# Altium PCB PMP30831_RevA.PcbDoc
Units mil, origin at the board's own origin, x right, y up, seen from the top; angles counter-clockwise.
Board outline 4950 x 2150 mil, 2 copper layers (Top Layer, Bottom Layer), stack 62 mil thick; 78 components, 43 nets, 171 pads, 14 vias.
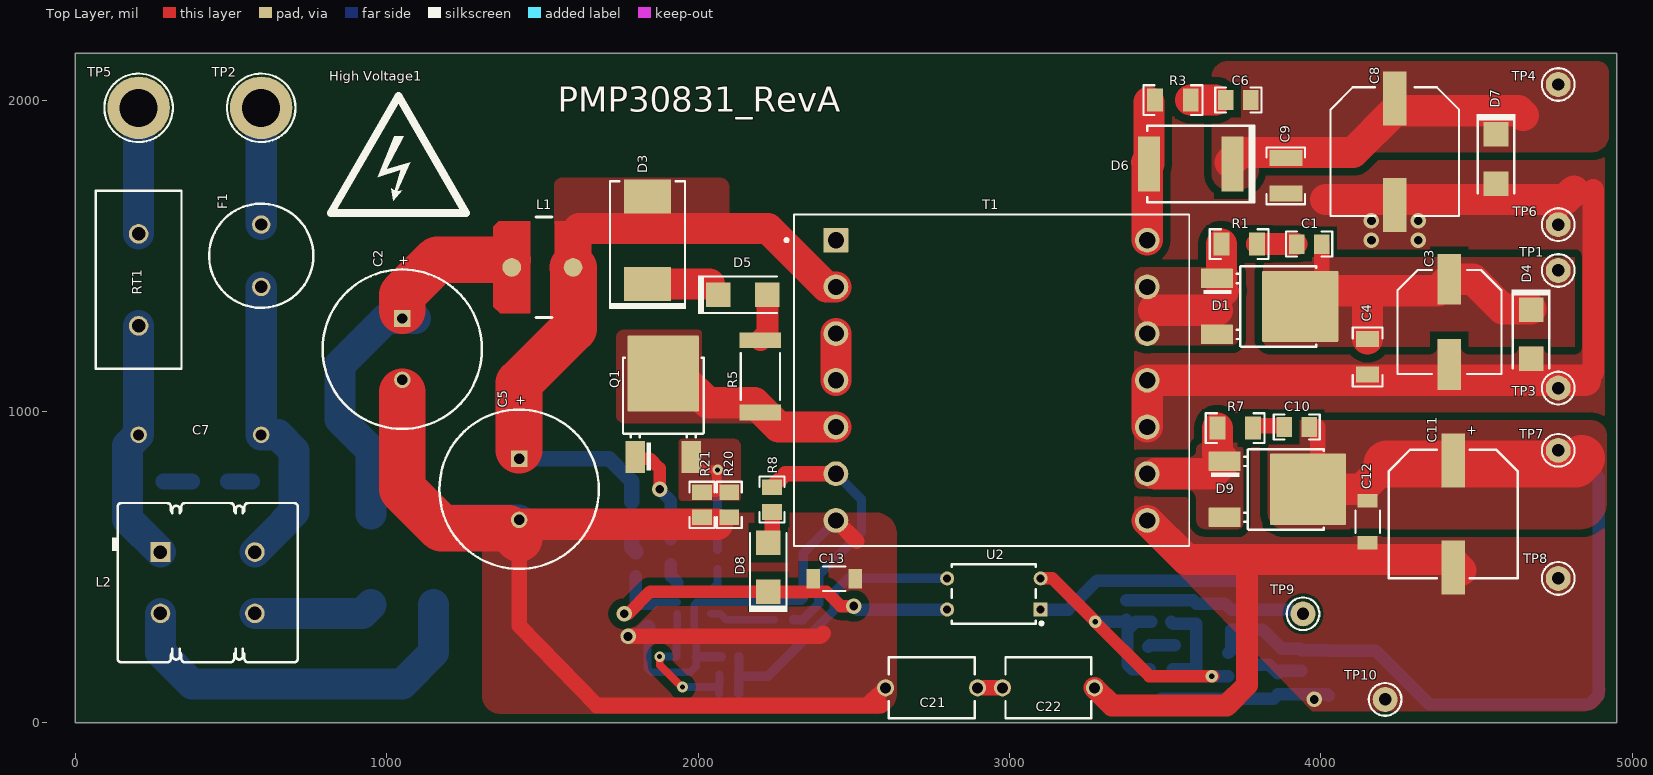
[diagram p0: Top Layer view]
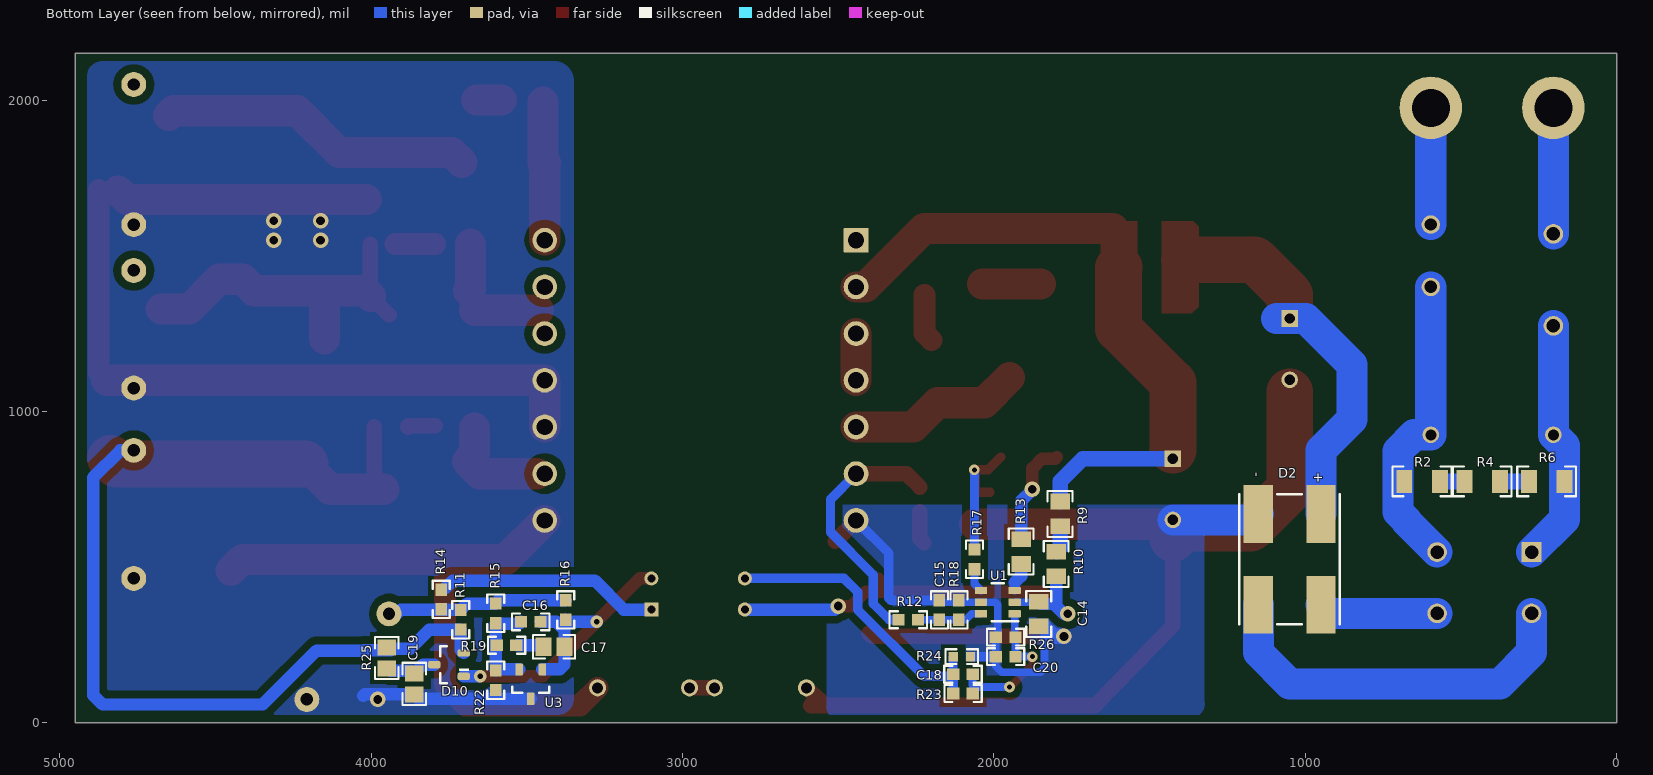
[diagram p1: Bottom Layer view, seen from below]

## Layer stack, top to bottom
Top Solder: solder mask 0.4, Solder Resist, Dk 3.5
Top Layer: signal copper 1.4
Dielectric1: core 59.2, FR-4, Dk 4.8
Bottom Layer: signal copper 1.4
Bottom Solder: solder mask 0.4, Solder Resist, Dk 3.5

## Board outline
0,0 4950,0 4950,2150 0,2150

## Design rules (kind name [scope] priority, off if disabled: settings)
AcuteAngle [All] p1: minimum=4.50000000000000E+0001 checktracksonly=FALSE
AssemblyTestPointUsage [All] p1: valid=2
BoardOutlineClearance BoardOutlineClearance_MountingHoles [OnCopper and InComponentClass('Mounting Holes')] p1: gap=39.37 ignorepadtopadclearanceinfootprint=FALSE
BoardOutlineClearance BoardOutlineClearance_Poly [OnCopper and IsPoly] p2: gap=25 ignorepadtopadclearanceinfootprint=FALSE
BoardOutlineClearance [OnCopper and Not InComponentClass('Logo') and not InComponentClass('FiducialMark') and not InRegion(1000,500,4000,800) and not InPoly] p3: gap=15 ignorepadtopadclearanceinfootprint=FALSE
Clearance Clearance_Keepouts [((IsTrack Or IsArc) And Not InPoly) And IsFree and IsKeepOut vs ((IsTrack Or IsArc) And Not InPoly) And IsFree and IsKeepOut] p1: gap=0 ignorepadtopadclearanceinfootprint=FALSE
Clearance Clearance_Poly [InPolygon] p2: gap=25 ignorepadtopadclearanceinfootprint=TRUE
Clearance Clearance_FiducialMark [IsKeepOut and InComponentClass('FiducialMark') vs IsPad and InComponentClass('FiducialMark')] p3: gap=0 ignorepadtopadclearanceinfootprint=FALSE
Clearance [All] p4: gap=7 ignorepadtopadclearanceinfootprint=TRUE
ComponentClearance ComponentClearance_MountingHoles_FiducialMarks [InComponentClass('Mounting Holes') vs InComponentClass('FiducialMark')] p1: gap=50 collisioncheckmode=3 verticalgap=10 showdistances=FALSE
ComponentClearance ComponentClearance_Shunt [InComponentClass('Header') vs InComponentClass('Shunt')] p2: gap=0 collisioncheckmode=3 verticalgap=0 showdistances=FALSE
ComponentClearance ComponentClearance_Logo [InComponentClass('Logo')] p3: gap=50 collisioncheckmode=3 verticalgap=10 showdistances=FALSE
ComponentClearance ComponentClearance_ScrewToNut [(HasFootprint('NY PMS 440 0025 PH')) vs (HasFootprint('Keystone_1902C'))] p4: gap=5 collisioncheckmode=3 verticalgap=10 showdistances=FALSE
ComponentClearance ComponentClearance_MountingHoles [InComponentClass('Mounting Holes')] p5: gap=250 collisioncheckmode=3 verticalgap=100000 showdistances=FALSE
ComponentClearance ComponentClearance_SmallPassives [HasFootprint('0201*') or HasFootprint('0402*') or HasFootprint('0508') or HasFootprint('0603*') or HasFootprint('0612') or HasFootprint('0805*') or HasFootprint('0815*') or HasFootprint('0830*') or HasFootprint('1206*') or HasFootprint('1210*') or HasFootprint('1808*') or HasFootprint('1812*') or HasFootprint('1825*') or HasFootprint('2010*') or HasFootprint('2220*') or HasFootprint('2225*') or HasFootprint('2512*') or HasFootprint('2728*') or HasFootprint('3518*') vs HasFootprint('0201*') or HasFootprint('0402*') or HasFootprint('0508') or HasFootprint('0603*') or HasFootprint('0612') or HasFootprint('0805*') or HasFootprint('0815*') or HasFootprint('0830*') or HasFootprint('1206*') or HasFootprint('1210*') or HasFootprint('1808*') or HasFootprint('1812*') or HasFootprint('1825*') or HasFootprint('2010*') or HasFootprint('2220*') or HasFootprint('2225*') or HasFootprint('2512*') or HasFootprint('2728*') or HasFootprint('3518*')] p6: gap=14.96 collisioncheckmode=3 verticalgap=10 showdistances=FALSE
ComponentClearance ComponentClearance_THtoSMT [IsThruComponent vs IsSMTComponent] p7: gap=40 collisioncheckmode=3 verticalgap=30 showdistances=FALSE
ComponentClearance ComponentClearance_THtoTH [IsThruComponent vs IsThruComponent] p8: gap=30 collisioncheckmode=3 verticalgap=30 showdistances=FALSE
ComponentClearance [All] p9: gap=15 collisioncheckmode=3 verticalgap=10 showdistances=FALSE
DiffPairsRouting [All] p1: maxlimit=100 minlimit=10 mostfreqgap=10 toplayer_minwidth=15 toplayer_maxwidth=15 toplayer_prefwidth=15 bottomlayer_minwidth=15 bottomlayer_maxwidth=15 bottomlayer_prefwidth=15 maxuncoupledlength=1000
FabricationTestPointUsage TestPointUsage [All] p1: valid=2 allowmultiple=FALSE
FabricationTestpoint Testpoint [All] p1: side=3 testpointundercomponent=TRUE minsize=40 maxsize=100 preferedsize=60 minholesize=0 maxholesize=40 preferedholesize=32 testpointgrid=1 allowsidetop=TRUE allowsidebottom=TRUE usegrid=TRUE gridtolerance=0.01
FanoutControl Fanout_LCC [IsLCC] p1: bgadir=Out bgaviamode=Centered fanoutstyle=Auto fanoutdirection=Alternating viagrid=1 // Fanout_LCC (Default Rule)
FanoutControl Fanout_BGA [IsBGA] p2: bgadir=Out bgaviamode=Centered fanoutstyle=Auto fanoutdirection=Alternating viagrid=1 // Fanout_BGA (Default Rule)
FanoutControl Fanout_Default [All] p4: bgadir=Out bgaviamode=Centered fanoutstyle=Auto fanoutdirection=Alternating viagrid=1 // Fanout_Default (Default Rule)
FanoutControl Fanout_Small [(CompPinCount < 5)] p5: bgadir=Out bgaviamode=Centered fanoutstyle=Auto fanoutdirection=OutThenIn viagrid=1 // Fanout_Small (Default Rule)
HoleSize [All] p1: absolutevalues=TRUE maxlimit=251 minlimit=7.87 maxpercent=80.000 minpercent=20.000
MinimumAnnularRing MinimumAnnularRing_ThermalPadVias [IsVia and InAnyComponent] p1: minimumring=5.91
MinimumAnnularRing [All] p2: minimumring=7.87
MinimumSolderMaskSliver MinimumSolderMaskSliver_Logo [InComponentClass('Logo') vs InComponentClass('Logo')] p1: minsoldermaskwidth=0.7
MinimumSolderMaskSliver [All] p2: minsoldermaskwidth=3.94
PlaneConnect [All] p1: planeconnectstyle=Relief reliefexpansion=10 reliefentries=4 reliefconductorwidth=10 reliefairgap=10
PolygonConnect [All] p1: connectstyle=Direct reliefconductorwidth=10 reliefentries=4 polygonreliefangle="90 Angle" airgapwidth=10
RoutingVias ThermalPadVias [IsVia and InAnyComponent] p1: holewidth=7.87 width=19.68 viastyle="Through Hole" minholewidth=7.87 minwidth=19.68 maxholewidth=12.99 maxwidth=23.62
RoutingVias [All] p2: holewidth=28 width=40 viastyle="Through Hole" minholewidth=10 minwidth=28 maxholewidth=28 maxwidth=50
SilkToBoardRegionClearance [Not ((IsComment or IsDesignator) And (Hide <> 'False')) and not InRegion(1000,500,4000,800)] p1:
SilkToSilkClearance SilkToSilkClearance_Pb-FreeLogo [(HasFootprint('Pb-Free_Overlay_Medium') OR HasFootprint('Pb-Free_Overlay_Small')) vs (HasFootprint('Pb-Free_Overlay_Medium') OR HasFootprint('Pb-Free_Overlay_Small'))] p1: silktosilkclearance=0
SilkToSilkClearance [All] p2: silktosilkclearance=0.1
SilkToSolderMaskClearance SilkToComponentPadClearance [(IsPad or IsFill or IsRegion) and InAnycomponent] p1: minsilkscreentomaskgap=0.1 clearancetoexposedcopper=TRUE
SilkToSolderMaskClearance "Silk to Solder Mask Opening" [All] p2: minsilkscreentomaskgap=0.1 clearancetoexposedcopper=FALSE
SolderMaskExpansion [All] p1: expansion=1.97
UnRoutedNet [All] p1: checkbadconnections=TRUE
Width [All] p1: maxlimit=150 minlimit=6 preferedwidth=10 checkconnectedcopper=TRUE
14 further rules are at their usual default settings.

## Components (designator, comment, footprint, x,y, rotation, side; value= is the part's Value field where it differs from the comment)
C1 "DNP" 0805_HV 3962.5,1537.5 r0 top
C2 "UCS2G220MHD" UCS_1250x2000 1050,1200 r270 top value=22uF
C3 "16SVPF270M" SVPF_E7 4412.5,1287.5 r270 top value=270uF
C4 "C1206C225K4RACTU" 1206 4150,1175 r270 top value=2.2uF
C5 "UCS2G220MHD" UCS_1250x2000 1425,750 r270 top value=22uF
C6 "DNP" 0805_HV 3735,2000 r0 top
C7 "890324023023" WCAP-FTX2_1300x700x1300 400,925 r180 top value=0.1uF
C8 "25SVP22M" SM_RADIAL_10AMM 4237.5,1834.22 r270 top value=DNP
C9 "GRM32DR71E106KA12L" 1210_220 3887.5,1756.72 r270 top value=10uF
C10 "DNP" 0805_HV 3922.5,950 r0 top
C11 "35SVPF120M" CAPSMT_62_F12 4425,670.69 r270 top value=120uF
C12 "GRM31CR71H225KA88L" 1206_180 4150,645.57 r270 top value=2.2uF
C13 "GRM31CR71H475KA12L" 1206_180 2437.5,462.5 r0 top value=4.7uF
C14 "C0805C105K5RACTU" 0805_HV 1856,349.45 r270 bottom value=1uF
C15 "Used in BOM report" 0603 2175,362.5 r90 bottom value=DNP
C16 "GRM188R71H223KA01D" 0603 3487.5,324.21 r180 bottom value=0.022uF
C17 "Used in BOM report" 0805 3412.5,244.19 r0 bottom value=DNP
C18 "GRM188R71H682KA01D" 0603 2099.26,155.98 r180 bottom value=6800pF
C19 "Used in BOM report" 0805 3861.71,125 r270 bottom value=DNP
C20 "Used in BOM report" 0603 1962.5,212.5 r0 bottom value=DNP
C21 "DE2E3KY152MN3AM02F" KY_700x500x1000 2750,112.5 r180 top value=1500pF
C22 "DE2E3KY152MN3AM02F" KY_700x500x1000 3125,112.5 r180 top value=1500pF
D1 "V20PW60" DPAK 3800,1337.5 r0 top
D2 "Z4DGP406L-HF" Z4-D 1050,525 r270 bottom value=600V
D3 "SMCJ150A-TP" SMC 1837.5,1550 r90 top value=150V
D4 "1SMA5926BT3G" SMA 4675,1247.74 r270 top value=11V
D5 "ES1G-13-F" SMA 2143.75,1375 r0 top value=400V
D6 "30BQ150TR" SMC_295 3582.09,1794.59 r180 top value=150V
D7 "3SMAJ5933B-TP" SMA 4562.5,1810.67 r270 top value=22V
D8 "ES1D-13-F" SMA 2225,500 r90 top value=200V
D9 "STD15150" DPAK 3825,750 r0 top
D10 "DNP" SOT-23 3750,186.71 r0 bottom
F1 "37212500001" FUSE_372 596.85,1500 r90 top
"High Voltage1" "DANGER HIGH VOLTAGE" IEC_HighVoltage_Medium 1037.5,1812.5 r0 top
L1 "74477510" WE-PD2-L 1500,1462.5 r0 top value=10uH
L2 "744822222" WE-CMB_Type_S 425,450 r0 top value=2.2mH
Q1 "IPD60R600C6ATMA1" DPAK 1887.99,987.5 r90 top value=600V
R1 "DNP" 1206 3737.5,1537.5 r180 top
R2 "Used in BOM report" 1206 625,775 r0 bottom value=DNP
R3 "DNP" 1206 3525,2000 r180 top
R4 "Used in BOM report" 1206 432.09,775 r0 bottom value=DNP
R5 "CRCW251249R9FKEG" 2512 2200,1112.5 r90 top value=49.9
R6 "Used in BOM report" 1206 225,775 r0 bottom value=DNP
R7 "DNP" 1206 3725,946.72 r180 top
R8 "CRCW080533R0JNEA" 0805_HV 2237.5,716.93 r90 top value=33
R9 "CRCW08054M99FKEA" 0805_HV 1787.5,670.67 r90 bottom value=4.99Meg
R10 "CRCW08054M99FKEA" 0805_HV 1800,510 r90 bottom value=4.99Meg
R11 "CRCW060349R9FKEA" 0603 3712.5,331 r270 bottom value=49.9
R12 "CRCW0603237KFKEA" 0603 2275,331 r0 bottom value=237k
R13 "CRCW080510R0FKEA" 0805_HV 1912.5,550 r90 bottom value=10.0
R14 "CRCW06031K50FKEA" 0603 3775,396.18 r270 bottom value=1.50k
R15 "CRCW0603200KFKEA" 0603 3600,351.57 r90 bottom value=200k
R16 "CRCW06033K01FKEA" 0603 3375,362.5 r90 bottom value=3.01k
R17 "CRCW06031K87FKEA" 0603 2062.5,525 r90 bottom value=1.87k
R18 "CRCW060348K7FKEA" 0603 2112.5,362.5 r270 bottom value=48.7k
R19 "Used in BOM report" 0603 3565.26,249.21 r180 bottom value=DNP
R20 "DNP" 0805_HV 2100,700 r90 top
R21 "ERJ-6RQFR39V" 0805_HV 2012.5,700 r90 top value=0.39
R22 "CRCW060323K2FKEA" 0603 3600,136.71 r90 bottom value=23.2k
R23 "CRCW060332K4FKEA" 0603 2099.03,93.88 r0 bottom value=32.4k
R24 "DNP" 0603_HV 2103,212.5 r0 bottom
R25 "Used in BOM report" 0805 3950,208.46 r270 bottom value=DNP
R26 "CRCW06034K02FKEA" 0603 1962.5,275 r180 bottom value=4.02k
RT1 "SHORT" TDK_B572 203.15,1422.64 r270 top
T1 "750319059r00" FP-750319059r00_PTH_XFRMR_32MM25_27MM05-MFG 2942.52,1100 r0 top
TP1 "5000" Keystone5000 4762.5,1452.69 r90 top
TP2 "Suggest using a net name here" Keystone1503-2 596.85,1975 r270 top value=Double
TP3 "5001" Keystone5001 4762.5,1075 r90 top
TP4 "5000" Keystone5000 4762.5,2050 r90 top
TP5 "Suggest using a net name here" Keystone1503-2 203.15,1975 r270 top value=Double
TP6 "5001" Keystone5001 4762.5,1600 r90 top
TP7 "5000" Keystone5000 4762.5,875 r90 top
TP8 "5001" Keystone5001 4762.5,463.74 r90 top
TP9 "5000" Keystone5000 3942.72,350 r90 top
TP10 "5001" Keystone5001 4206.5,75 r90 top
U1 "UCC28742DBVR" DBV0006A_N 1987.5,387.5 r0 bottom
U2 "FOD817A" DIP-4 2950,413.74 r180 top
U3 "ATL431LIBQDBZR" DBZ0003A_N 3487.5,124.21 r270 bottom

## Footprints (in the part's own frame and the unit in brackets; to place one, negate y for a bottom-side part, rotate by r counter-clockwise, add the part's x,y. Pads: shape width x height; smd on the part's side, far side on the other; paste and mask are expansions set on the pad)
0603 [mm] "0603 from SM-752 data"
  rect 1x0.95 smd: 1(-0.8,0) 2(0.8,0)
  silkscreen extent -1.52,-0.69 1.52,0.69, body extent -0.87,-0.47 0.87,0.47, height 1
0603_HV [mil] "Ernesto recommended land pattern.  26 mil between pads."
  rect 30x30 smd: 1(-28,0) 2(28,0)
  silkscreen extent -52,-24 52,24, body extent -34,-19 34,19, height 39
0805 [mm] "0805 from SM-752 data"
  rect 1.3x1.5 smd: 1(-0.85,0) 2(0.85,0)
  silkscreen extent -1.72,-0.97 1.72,0.97, body extent -1.1,-0.72 1.1,0.72, height 1.45
0805_HV [mil] "0805 with 30mil clearance between pads"
  rect 50x63 smd: 1(-40,0) 2(40,0)
  silkscreen extent -74,-40 74,40, body extent -43,-29 43,29, height 57
1206 [mm] "1206 from SM-752 data"
  rect 1.3x1.85 smd: 1(-1.45,0) 2(1.45,0)
  silkscreen extent -2.4,-1.21 2.4,1.21, body extent -1.7,-0.9 1.7,0.9, height 1.35
1206_180 [mm] "1206_180"
  rect 1.1x1.6 smd: 1(-1.7,0) 2(1.7,0)
  silkscreen extent -0.9,-1 0.9,1, body extent -1.75,-0.95 1.75,0.95, height 1.8
1210_220 [mm] "1210"
  rect 1.3x2.7 smd: 1(-1.45,0) 2(1.45,0)
  silkscreen extent -2.32,-1.57 2.32,1.57, body extent -1.7,-1.35 1.7,1.35, height 2.2
2512 [mm] "Chip Resistor, Body 6.3x3.2mm, IPC Medium Density"
  rect 1.3x3.4 smd: 1(-2.95,0) 2(2.95,0)
  silkscreen extent -1.9,-1.6 1.9,1.6, body extent -3.22,-1.67 3.22,1.67, height 0.71
CAPSMT_62_F12 [mm] "F12, SMD, 2-Leads, Body 10.5x10.5mm, Height 12.7mm"
  rect 4.4x1.9 smd: 1(-4.35,0) 2(4.35,0)
  silkscreen extent -5.25,-5.25 5.25,5.25, body extent -5.25,-5.25 5.25,5.25, height 12.71
DBV0006A_N [mm] "SOT23, 6-Leads, Body 2.9x1.6mm, Pitch 0.95mm, Lead Span 2.8mm, IPC Medium Density"
  rrect17% 1x0.6 smd: 1(-1.375,0.95) 2(-1.375,0) 3(-1.375,-0.95) 4(1.375,-0.95) 5(1.375,0) 6(1.375,0.95)
  silkscreen extent -1.68,-1.55 0.5,1.55, body extent -1.42,-1.46 1.42,1.46, height 1.12
DBZ0003A_N [mm] "SOT23, 3-Leads, Body 2.9x1.3mm, Pitch 0.95mm, Lead Span 2.4mm, IPC Medium Density"
  rrect17% 1x0.6 smd: 1(-1.2,0.95) 2(-1.2,-0.95) 3(1.2,0)
  silkscreen extent 0.2,-1.5 0.7,1.5, body extent -1.26,-1.46 1.26,1.46, height 0.98
DIP-4 [mm] "DIP, 4-Leads, Body 6.86x4.83mm, Pitch 2.54mm"
  rect 1.15x1.15 hole 0.65: 1(-3.81,1.27)
  round 1.15 hole 0.65: 2(-3.81,-1.27) 3(3.81,-1.27) 4(3.81,1.27)
  silkscreen extent -4,-2.41 3.43,2.52, body extent -4.02,-2.41 4.02,2.41, height 5.59
DPAK [mm] "D-PAK, 3-Pads, Body 6.22x6.73mm (max), TO-252AA using nominal STEP model"
  rrect6% 2.6x1.6 smd: 1(-3.4,2.28) 3(-3.4,-2.28)
  rrect2% 6.2x5.8 smd paste-2.9: 4(3.4,0)
  silkscreen extent -4.5,-3.3 4.7,3.28, body extent -3.86,-3.29 5.84,3.29, height 2.48
FP-750319059r00_PTH_XFRMR_32MM25_27MM05-MFG [mm]
  rrect5% 2.02x2.02 hole 1.32 paste-1000 mask+0: 1(-12.7,11.43)
  round 2.02 hole 1.32 paste-1000 mask+0: 2(-12.7,7.62) 3(-12.7,3.81) 4(-12.7,0) 5(-12.7,-3.81) 6(-12.7,-7.62) 7(-12.7,-11.43) 8(12.7,-11.43) 9(12.7,-7.62) 10(12.7,-3.81) 11(12.7,0) 12(12.7,3.81) 13(12.7,7.62) 14(12.7,11.43)
  silkscreen extent -16.85,-13.52 16.12,13.52, body extent -16.22,-13.62 16.22,13.62, height 0.25
FUSE_372 [mm] "LITTELFUSE"
  round 1.5 hole 1: 1(-2.54,0) 2(2.54,0)
  silkscreen extent -4.25,-4.25 4.25,4.25, body extent -4.25,-4.25 4.25,4.25, height 8
IEC_HighVoltage_Medium [mil]
  silkscreen extent -217,-176 217,200
Keystone1503-2 [mm] "Double Turret"
  round 5.1 hole 3.1: 1(0,0)
  silkscreen extent -2.79,-2.79 2.79,2.79, body extent -2.4,-2.4 2.38,2.4, height 9.22
Keystone5000 [mil] "For Keystone 500x miniature loop terminals"
  round 80 hole 40: 1(0,0)
  silkscreen extent -52,-52 52,52, body extent -49,-49 49,49, height 182
Keystone5001 [mil] "For Keystone 500x miniature loop terminals"
  round 80 hole 40: 1(0,0)
  silkscreen extent -52,-52 52,52, body extent -49,-49 49,49, height 182
KY_700x500x1000 [mm] "TH, 2- Leads, Body 7x5mm, Pin Spacing 7.5mm"
  round 1.4 hole 0.9: 1(-3.75,0) 2(3.75,0)
  silkscreen extent -3.5,-2.5 3.5,2.5, body extent -4.05,-2.5 4.05,2.5, height 9.97
SM_RADIAL_10AMM [mm] "10 x 7.9mm:  Sanyo Oscon F8"
  rect 4.4x1.9 smd: 1(-4.35,0) 2(4.35,0)
  silkscreen extent -5.25,-5.25 5.25,5.25, body extent -5.25,-5.25 5.25,5.25, height 8
SMA [mm] "Molded Diode, 2-Leads, Body 4.3x2.6mm, IPC Medium Density, based on OnSemi component dimensions and land pattern"
  rect 2x2 smd: 1(-2,0) 2(2,0)
  silkscreen extent -3.66,-1.57 2.79,1.57, body extent -2.6,-1.3 2.6,1.3, height 2.42
SMC [mil] "Molded Diode, 2-Leads, Body 6.9x5.8mm, IPC Medium Density, based on OnSemi component dimensions and land patterns"
  rect 110x150 smd: 1(-140.49,0) 2(140.49,0)
  silkscreen extent -221,-124 189,123, body extent -156,-116 156,116, height 91
SMC_295 [mm] "SMD, 2-Leads, Body 5.905x6.855mm"
  rect 1.77x4.5 smd: 1(-3.41,0) 2(3.41,0)
  silkscreen extent -5.3,-3.11 3.55,3.11, body extent -4,-3.11 4,3.11, height 2.96
SOT-23 [mm] "SOT23, 3-Leads, Body 2.9x1.3mm, Pitch 0.95mm, Lead Span 2.5mm, IPC Medium Density"
  rrect50% 1x0.6 smd: 1(-1.2,0.95) 2(-1.2,-0.95) 3(1.2,0)
  silkscreen extent -1.63,-1.5 0.7,1.5, body extent -1.16,-1.45 1.21,1.45, height 1
SVPF_E7 [mm] "Panasonic SVPF series"
  rect 4.15x1.9 smd: 1(-3.475,0) 2(3.475,0)
  silkscreen extent -4.24,-4.24 4.26,4.26, body extent -4.24,-4.24 4.26,4.26, height 7
TDK_B572 [mm] "TH, 2-Leads, Dia 14.5mm, Pin Spacing 7.5mm"
  round 1.6 hole 1.1: 1(-3.75,0) 2(3.75,0)
  silkscreen extent -7.25,-3.5 7.25,3.5, body extent -7.25,-3.5 7.19,3.5, height 21.99
UCS_1250x2000 [mm] "TH, 2-Leads, Dia 12.5mm, Pin Spacing 5mm"
  rect 1.35x1.35 hole 0.85: 1(-2.5,0)
  round 1.35 hole 0.85: 2(2.5,0)
  silkscreen extent -6.5,-6.5 6.5,6.5, body extent -6.5,-6.5 6.51,6.5, height 21.51
WCAP-FTX2_1300x700x1300 [mm] "TH, 2-Leads, Body 13x7mm, Pin Spacing 10mm"
  round 1.35 hole 0.9: 1(-5,0) 2(5,0)
  body extent -6.5,-3.5 6.5,3.5, height 13
WE-CMB_Type_S [mm] "TH, 4-Leads, Body 14.7x13mm"
  rect 1.6x1.6 hole 1.1: 1(-3.85,2.5)
  round 1.6 hole 1.1: 2(-3.85,-2.5) 3(3.85,-2.5) 4(3.85,2.5)
  silkscreen extent -7.8,-6.5 7.35,6.5, body extent -7.77,-6.5 7.77,6.5, height 20
WE-PD2-L [mil] "WE, Inductor"
  round 60 smd: 1(-98.43,0) 2(98.43,0)
  Top Layer region: 39.37,147.64 39.37,-147.64 139.76,-147.64 157.48,-129.92 157.48,125.98 135.83,147.64
  Top Layer region: -39.37,-147.64 -39.37,147.64 -139.76,147.64 -157.48,129.92 -157.48,-125.98 -135.83,-147.64
  silkscreen extent -20,-161 30,161, body extent -157,-144 159,144, height 217
Z4-D [mm] "SMD, 4-Leads, Body 8.1x10.5mm"
  rect 4.7x2.4 smd: 1(-3.7,2.55) 2(3.7,2.55) 3(3.7,-2.55) 4(-3.7,-2.55)
  silkscreen extent -5.3,-4.1 5.3,4.1, body extent -5.3,-4.1 5.3,4.1, height 1.56

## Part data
C1 C6 C10: library part Capacitor, "CAP, CERM, xxxF, xxV, [TempCo], xx%, [PackageReference]", Alternate Manufacturer=-, Manufacturer="Used in BOM report"
C2 C5: library part CMP-0081925-1, "CAP, AL, 22 µF, 400 V, +/- 20%, TH", Cap_Case=12.5x20mm, Manufacturer=Nichicon, Supplier Part Number 1=493-5875-ND, Tolerance_%=20%, Value2=400V, ValueDisplayed=22µF
C3: library part CMP-0012093-3, "CAP, Aluminum Polymer, 270 uF, 16 V, +/- 20%, 0.022 ohm, 8.0x7.0mm SMD", Manufacturer=Panasonic, Supplier Part Number 1=P16480CT-ND, Tolerance_%=20%, Value1="0.022 ohm", Value2=16V, ValueDisplayed=270uF
C4: "CAP, CERM, 2.2 µF, 16 V,+/- 10%, X7R, 1206", Cap_Case=1206, Manufacturer=Kemet, Supplier Part Number 1=80-C1206C225K4R, TempCo=X7R, Tolerance_%=10, Value1="0.009 ohm", Value2=16V, ValueDisplayed=2.2µF
C7: library part CMP-0081647-2, "CAP, Film, 0.1 µF,  V,+/- 10%, TH", Cap_Case=13x7x13mm, Manufacturer="Wurth Elektronik", Supplier Part Number 1=732-5883-ND, Tolerance_%=10%, ValueDisplayed=0.1µF
C8: library part CMP-0012114-3, "CAP, Aluminum Polymer, 22 uF, 25 V, +/- 20%, 0.05 ohm, 10x10.3 SMD", Cap_Case=10.3x10.3x7.9, Manufacturer=Panasonic, PartNumber=DNP, Tolerance_%=20%, Value1="0.05 ohm", Value2=25V
C9: "CAP, CERM, 10 µF, 25 V,+/- 10%, X7R, 1210", Cap_Case=1210, Manufacturer=MuRata, Supplier Part Number 1=490-1867-1-ND, TempCo=X7R, Tolerance_%=10, Value2=25V, ValueDisplayed=10µF
C11: library part CMP-0012133-1, "CAP, Aluminum Polymer, 120 uF, 35 V, +/- 20%, 0.018 ohm, F12, SMD, 2-Leads, Body 10.5x10.5mm, Height 12.7mm SMD", Cap_Case=F12, Manufacturer=Panasonic, Tolerance_%=20%, Value1="0.018 ohm", Value2=35V, ValueDisplayed=120uF
C12: "CAP, CERM, 2.2 µF, 50 V,+/- 10%, X7R, 1206", Cap_Case=1206, Manufacturer=MuRata, Supplier Part Number 1=490-3367-1-ND, TempCo=X7R, Tolerance_%=10, Value2=50V, ValueDisplayed=2.2µF
C13: "CAP, CERM, 4.7 µF, 50 V,+/- 10%, X7R, 1206", Cap_Case=1206, Manufacturer=MuRata, Supplier Part Number 1=24R6347, TempCo=X7R, Tolerance_%=10, Value2=50V, ValueDisplayed=4.7µF
C14: "CAP, CERM, 1 µF, 50 V,+/- 10%, X7R, 0805", Cap_Case=0805, Manufacturer=Kemet, Supplier Part Number 1=399-7409-1-ND, TempCo=X7R, Tolerance_%=10, Value2=50V, ValueDisplayed=1µF
C15 C17 C19 C20: library part Capacitor, "CAP, CERM, xxxF, xxV, [TempCo], xx%, [PackageReference]", Alternate Manufacturer=-
C16: "CAP, CERM, 0.022 µF, 50 V,+/- 10%, X7R, 0603", Cap_Case=0603, Manufacturer=MuRata, Supplier Part Number 1=490-1517-1-ND, TempCo=X7R, Tolerance_%=10, Value2=50V, ValueDisplayed=0.022µF
C18: "CAP, CERM, 6800 pF, 50 V,+/- 10%, X7R, 0603", Cap_Case=0603, Manufacturer=MuRata, Supplier Part Number 1=490-1508-1-ND, TempCo=X7R, Tolerance_%=10, Value2=50V, ValueDisplayed=6800pF
C21 C22: "CAP, CERM, 1500 pF, X1 250 VAC/Y2 300 VAC, +/- 20%, E, TH, 2- Leads, Body 7x5mm, Pin Spacing 7.5mm", Cap_Case=7x5x10mm, Manufacturer=MuRata, Supplier Part Number 1=490-9553-1-ND, TempCo=E, Tolerance_%=20, ValueDisplayed=1500pF
D1: library part DIODE_SCHOTTKY_A13C4, "Diode, Schottky,60V,20A, [PackageReference]", Alternate Manufacturer=-, Manufacturer=Vishay
D2: library part CMP-0029244-3, "Diode, P-N-Bridge, 600 V, 4 A, Z4-D", Manufacturer="Comchip Technology", Value1=4A, Value2=0.95V
D3: "Diode, TVS, Uni, 150 V, 243 Vc, SMC", Manufacturer="Micro Commercial Components", Supplier Part Number 1=SMCJ150A-TPMSCT-ND, Value1=W
D4: "Diode, Zener, 11 V, 1.5 W, SMA", Manufacturer="ON Semiconductor", Power_W=1.5, Supplier Part Number 1=45W9639, Value1=1.5W
D5: "Diode, Superfast Rectifier, 400 V, 1 A, SMA", Manufacturer="Diodes Inc.", Supplier Part Number 1=ES1G-FDICT-ND, Value1=1A, Value2=1.25V
D6: library part CMP-0083842-2, "Diode, Schottky, 150 V, 3 A, SMC", Manufacturer="SMC Diode Solutions", Value1=3A, Value2=0.86V
D7: "Diode, Zener, 22 V, 3 W, SMA", Manufacturer="Micro Commercial Components", Power_W=3, Supplier Part Number 1=3SMAJ5933B-TPMSCT-ND, Value1=3W
D8: "Diode, Ultrafast, 200 V, 1 A, SMA", Manufacturer="Diodes Inc.", Supplier Part Number 1=ES1D-FDICT-ND, Value1=1A, Value2=0.92V
D9: library part DIODE_SCHOTTKY_A13C4, "Diode, Schottky,150V,15A, [PackageReference]", Alternate Manufacturer=-, Manufacturer="SMC Diode Solutions"
D10: library part BAT54S-7-F, "Diode, Schottky, 30 V, 0.2 A, SOT-23", Manufacturer="Diodes Inc.", Supplier Part Number 1=BAT54S-FDICT-ND, Value1=0.2A, Value2=0.65V
F1: library part CMP-0003556-2, "Fuse, 2.5 A, 250VAC/VDC, TH", Irating_A=2.5A, Manufacturer=Littelfuse, Supplier Part Number 1=WK6276CT-ND
"High Voltage1": library part IEC_HighVoltage, "IEC 61010-1 High Voltage Warning"
L1: library part CMP-0064260-1, "Inductor, Shielded Drum Core, Ferrite, 10 uH, 2.3 A, 0.07 ohm, SMD", Manufacturer="Wurth Elektronik", Supplier Part Number 1=732-1284-1-ND, Value1="0.07 ohm", Value2=2.3A, ValueDisplayed=10uH
L2: library part CMP-0013143-1, "Coupled inductor, 2.2 mH,  A, 0.07 ohm, TH", Manufacturer="Wurth Elektronik", Supplier Part Number 1=732-1440-ND, ValueDisplayed=2.2mH
Q1: library part CMP-0001165-1, "MOSFET, N-CH, 600 V, 7.3 A, AEC-Q101, DPAK", Alternate Manufacturer=None, Manufacturer="Infineon Technologies", Supplier Part Number 1=IPD60R600C6ATMA1CT-ND, Value2="20.5 nC"
R1 R3 R7 R20 R24: library part Resistor, "RES, xxx ohm, x%, xW, [PackageReference]", Alternate Manufacturer=-, Manufacturer="Used in BOM report"
R2 R4 R6 R19 R25: library part Resistor, "RES, xxx ohm, x%, xW, [PackageReference]", Alternate Manufacturer=-
R5: "RES, 49.9, 1%, 1 W, AEC-Q200 Grade 0, 2512", Manufacturer=Vishay-Dale, Power_W=1, Supplier Part Number 1=541-49.9AFCT-ND, TempCo="100 ppm/C", Value1=1%, Value2=1W, Value_Code=49R9, ValueDisplayed=49.9
R8: "RES, 33, 5%, 0.125 W, 0805", Manufacturer=Vishay-Dale, Power_W=0.125, Supplier Part Number 1=541-33ACT-ND, TempCo="200 ppm/C", Tolerance_%=5, Value1=5%, Value2=0.125W, Value_Code=33R0, ValueDisplayed=33
R9 R10: "RES, 4.99 M, 1%, 0.125 W, 0805", Manufacturer=Vishay-Dale, Power_W=0.125, Supplier Part Number 1=541-4.99MCCT-ND, TempCo="100 ppm/C", Tolerance_%=1, Value1=1%, Value2=0.125W, Value_Code=4M99, ValueDisplayed=4.99M
R11: "RES, 49.9, 1%, 0.1 W, 0603", Manufacturer=Vishay-Dale, Power_W=0.1, Supplier Part Number 1=541-49.9HCT-ND, TempCo="100 ppm/C", Tolerance_%=1, Value1=1%, Value2=0.1W, Value_Code=49R9, ValueDisplayed=49.9
R12: "RES, 237 k, 1%, 0.1 W, 0603", Manufacturer=Vishay-Dale, Power_W=0.1, Supplier Part Number 1=541-237KHCT-ND, TempCo="100 ppm/C", Tolerance_%=1, Value1=1%, Value2=0.1W, Value_Code=237k
R13: "RES, 10.0, 1%, 0.125 W, 0805", Manufacturer=Vishay-Dale, Power_W=0.125, Supplier Part Number 1=541-10.0CCT-ND, TempCo="100 ppm/C", Tolerance_%=1, Value1=1%, Value2=0.125W, Value_Code=10R0, ValueDisplayed=10.0
R14: "RES, 1.50 k, 1%, 0.1 W, 0603", Manufacturer=Vishay-Dale, Power_W=0.1, Supplier Part Number 1=541-1.50KHCT-ND, TempCo="100 ppm/C", Tolerance_%=1, Value1=1%, Value2=0.1W, Value_Code=1k50, ValueDisplayed=1.50k
R15: "RES, 200 k, 1%, 0.1 W, 0603", Manufacturer=Vishay-Dale, Power_W=0.1, Supplier Part Number 1=541-200KHCT-ND, TempCo="100 ppm/C", Tolerance_%=1, Value1=1%, Value2=0.1W, Value_Code=200k
R16: "RES, 3.01 k, 1%, 0.1 W, 0603", Manufacturer=Vishay-Dale, Power_W=0.1, Supplier Part Number 1=541-3.01KHCT-ND, TempCo="100 ppm/C", Tolerance_%=1, Value1=1%, Value2=0.1W, Value_Code=3k01, ValueDisplayed=3.01k
R17: "RES, 1.87 k, 1%, 0.1 W, 0603", Manufacturer=Vishay-Dale, Power_W=0.1, Supplier Part Number 1=541-1.87KHCT-ND, TempCo="100 ppm/C", Tolerance_%=1, Value1=1%, Value2=0.1W, Value_Code=1k87, ValueDisplayed=1.87k
R18: "RES, 48.7 k, 1%, 0.1 W, 0603", Manufacturer=Vishay-Dale, Power_W=0.1, Supplier Part Number 1=541-48.7KHCT-ND, TempCo="100 ppm/C", Tolerance_%=1, Value1=1%, Value2=0.1W, Value_Code=48k7, ValueDisplayed=48.7k
R21: "RES, 0.39, 1%, 0.125 W, 0805", Manufacturer=Panasonic, Power_W=0.125, Supplier Part Number 1=P.39DCT-ND, TempCo="250 ppm/C", Tolerance_%=1, Value1=1%, Value2=0.125W, Value_Code=R390, ValueDisplayed=0.39
R22: "RES, 23.2 k, 1%, 0.1 W, 0603", Manufacturer=Vishay-Dale, Power_W=0.1, Supplier Part Number 1=541-23.2KHCT-ND, TempCo="100 ppm/C", Tolerance_%=1, Value1=1%, Value2=0.1W, Value_Code=23k2, ValueDisplayed=23.2k
R23: "RES, 32.4 k, 1%, 0.1 W, 0603", Manufacturer=Vishay-Dale, Power_W=0.1, Supplier Part Number 1=541-32.4KHCT-ND, TempCo="100 ppm/C", Tolerance_%=1, Value1=1%, Value2=0.1W, Value_Code=32k4, ValueDisplayed=32.4k
R26: "RES, 4.02 k, 1%, 0.1 W, 0603", Manufacturer=Vishay-Dale, Power_W=0.1, Supplier Part Number 1=541-4.02KHCT-ND, TempCo="100 ppm/C", Tolerance_%=1, Value1=1%, Value2=0.1W, Value_Code=4k02, ValueDisplayed=4.02k
RT1: library part CMP-0002558-1, "Thermistor NTC, 5 ohm, 20%, D14.5xT7mm", Manufacturer=TDK, Power_W=3.8W, Supplier Part Number 1=94T3213, Tolerance_%=20%
T1: library part CMP-0088857-1, "TRANSFORMER", Frequency_Fixed=65kHz, Manufacturer="Wurth Electronics", Operating Temperature Range="-40°C to +125°C", Voltage_Isolation_Vrms=3.8kV
TP1 TP4 TP7 TP9: "Test Point, Miniature, Red, TH", Color=Red, Manufacturer=Keystone, Supplier Part Number 1=36-5000-ND
TP2 TP5: library part 1503-2, "Terminal, Turret, TH, Double", Manufacturer=Keystone, Supplier Part Number 1=1503-2K-ND
TP3 TP6 TP8 TP10: "Test Point, Miniature, Black, TH", Color=Black, Manufacturer=Keystone, Supplier Part Number 1=36-5001-ND
U1: library part CMP-0078369-2, "High-Efficiency Low-Cost Flyback Controller with Secondary-Side Regulation, DBV0006A (SOT-23-6)", Alternate Manufacturer="Texas Instruments"
U2: "Optocoupler, 5 kV, 80-160% CTR, TH", Manufacturer="Fairchild Semiconductor", Supplier Part Number 1=FOD817A-ND, Voltage_Isolation_Vrms=5000V
U3: library part CMP-0084731-1, "High Bandwidth Low-Iq Programmable Shunt Regulator, DBZ0003A (SOT-23-3)", Alternate Manufacturer="Texas Instruments"

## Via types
v1: diameter 50, hole 28, Top Layer to Bottom Layer, 9 vias
v2: diameter 34, hole 16, Top Layer to Bottom Layer, 3 vias
v3: diameter 40, hole 18, Top Layer to Bottom Layer, 2 vias

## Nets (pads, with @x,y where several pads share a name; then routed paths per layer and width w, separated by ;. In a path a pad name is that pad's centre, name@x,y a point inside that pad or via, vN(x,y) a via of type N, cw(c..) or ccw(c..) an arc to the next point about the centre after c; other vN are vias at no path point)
24Vout: C10.2 C11.1 C12.1 D9.4 D10.2 R11.2 R25.1 TP7.1 | length 3365.3
  Top Layer w50: D9.4 3960.71,751.85 ccw(c3890,822.56) 3990,822.56 3990,950
  Top Layer w100: D9.4 4131.24,750 4212.5,831.26
  Top Layer w150: 4212.5,831.26 4818.52,831.26 4837.26,850
  Bottom Layer w40: D10.2 3712.5,233.86 R11.2 3812.99,299.51 3875,237.5 3933.46,237.5 3937.5,233.46 4022.24,233.46 4023.61,232.1 4175,232.1 4348.29,58.81 4862.5,58.81 4892.76,89.07 4892.76,787.5 4805.26,875 TP7.1
GND: C3.2 C4.2 C8.2 C9.2 C11.2 C12.2 C19.2 C22.1 D4.2 D7.2 R22.1 T1.8 T1.10 T1.11 TP3.1 TP6.1 TP8.1 TP10.1 U3.3 | length 5517.9
  Top Layer w70: C22.1 3329.51,55.63 3696.97,55.63 3762.5,121.16 3762.5,525 ; 4875,1125 4875,1712.14
  Top Layer w100: T1.8 3567.52,525 3762.5,525 4413.74,525 C11.2@4450,488.74 ; T1.10 T1.11 4850,1100 ; 4015,1680.41 4784.41,1680.41 4812.5,1708.5
  Bottom Layer w40: U3.3 3847.93,76.97 C19.2@3862.11,91.14 ; C19.2 4020.96,91.54 4025,87.5
  other v1: 3979,75 4162.5,1550 4312.5,1550 4162.5,1612.5 4312.5,1612.5
NetC1_1: C1.1 R1.1 | length 127.9
  Top Layer w70: R1.1 C1.1
NetC1_2: C1.2 C3.1 C4.1 D1.4 D4.1 TP1.1 | length 1142
  Top Layer w50: D1.4@3942.72,1310.24 4002.5,1370.02 C1.2
  Top Layer w100: D1.4@4002.5,1370.02 4019.98,1387.5 4150,1387.5 ; C4.1 4150,1387.5 ; D4.1@4675,1328.74 4583.76,1328.74 4488.19,1424.31 C3.1 4375.69,1387.5 4150,1387.5
NetC2_1: C2.1 D2.1 L1.1 | length 1261.5
  Top Layer w150: C2.1@1050,1323.72 1050,1375 1162.5,1487.5 L1.1@1389.07,1487.5
  Bottom Layer w100: D2.1 949.61,875.39 850,975 850,1150 998.43,1298.43 C2.1 1092.52,1298.43
NetC5_1: C5.1 D3.2 L1.2 R9.2 T1.2 | length 2019.8
  Top Layer w100: 1618.31,1587.5 2225,1587.5 2412.5,1400 T1.2
  Top Layer w150: 1425,875 1425,1091.14 1600,1266.14 1600,1460.93 L1.2
  Bottom Layer w50: C5.1 1714.07,848.43 1787.5,775 R9.2
NetC6_1: C6.1 R3.1 | length 79.9
  Top Layer w100: R3.1 3661.96,2000
NetC6_2: C6.2 C8.1 C9.1 D6.1 D7.1 TP4.1 | length 1016
  Top Layer w100: D6.1@3709.25,1800 3741.34,1832.09 4103.74,1832.09 4237.5,1965.85 4337.5,1965.85 4634.15,1965.85 4650,1950
NetC7_1: C7.1 F1.1 L2.4 R2.2 | length 978
  Bottom Layer w100: L2.4 675,646.85 675,650 701.77,676.77 701.77,873.23 650,925 C7.1 F1.1
NetC7_2: C7.2 L2.1 R6.1 RT1.2 | length 784.9
  Bottom Layer w100: RT1.2 C7.2 167.91,889.76 R6.1 167.91,653.94 L2.1
NetC10_1: C10.1 R7.1 | length 90.5
  Top Layer w50: R7.1@3794.59,954.6 3877.9,954.6 cw(c3877.9,950) C10.1
NetC13_1: C13.1 C14.1 D8.1 R10.1 U1.2 U2.4 | length 1566.5
  Top Layer w40: v1(1762.5,350) 1775,350 1846.26,421.26 D8.1 ; C13.1 2370.57,425.95 2375,421.53 ; v1(2500,375) 2458.07,375 2411.55,421.53 2375,421.53 ; D8.1 2351.08,421.26 ; D8.1 2226.38,419.88 2349.7,419.88 2351.08,421.26 ; 2351.08,421.26 2351.35,421.53 2375,421.53 ; 2351.08,421.26 2374.73,421.26 2375,421.53
  Bottom Layer w25: C14.1@1850,381.5 1856,387.5 U1.2
  Bottom Layer w40: v1(1762.5,350) 1775,350 1800,375 ; R10.1 1800,375 ; C14.1@1850,381.5 1806.5,381.5 1800,375 ; v1(2500,375) 2511.26,363.74 U2.4
NetC15_1: C15.1 R12.1 R18.2 U1.6 | length 209.8
  Bottom Layer w25: U1.6 2071.36,350.1 2090.45,331 C15.1 R12.1
NetC16_1: C16.1 R15.1 R19.1 R22.2 U3.2 | length 309.6
  Bottom Layer w40: C16.1 3525.49,317.72 3600,317.72 R22.2 3596.75,171.46 U3.2
NetC16_2: C16.2 C17.1 D10.1 R16.1 U2.2 U3.1 | length 1113.3
  Top Layer w40: U2.2 3137.5,463.74 3275,326.24 v3(3275,324.57) 3449.57,150 v3@3655.31,150
  Bottom Layer w40: v3(3275,324.57) 3368.56,324.57 R16.1 ; U3.1 3394.29,171.46 3379.04,186.71 C17.1 3379.04,298.23 3405.02,324.21 C16.2 ; v3@3655.31,150 3702.07,150 D10.1
  other v3: 3650,150
NetC17_2: C17.2 R19.2 | length 87.1
  Bottom Layer w40: C17.2 3450.98,249.21 R19.2@3531,249.21
NetC18_1: C18.1 R23.2 R24.2 U2.3 | length 957
  Bottom Layer w30: R23.2 2130.75,94.1 C18.1 ; R24.2 2131.5,212 2131.5,150 2224.9,150 2437.5,362.6 2437.5,419.98 2481.26,463.74 U2.3
NetC18_2: C18.2 C20.1 R23.1 R26.2 U1.1 | length 523.3
  Top Layer w25: v2(1876.54,212.5) 1876.54,185.96 1887.5,175 1947.44,115.06 v2(1950,115.06)
  Bottom Layer w25: v2(1876.54,212.5) C20.1 R26.2 1933.37,277.36 U1.1 ; v2(1950,115.06) 2061.14,115.06 ; R23.1 2067.76,94.1 C18.2 ; 2068.5,122.42 C18.2@2068.5,150
NetC19_1: C19.1 D10.3 R25.2 | length 155.3
  Bottom Layer w40: D10.3 3833.46,186.71 C19.1 3869.78,166.54 R25.2@3937.5,166.54
NetC21_1: C21.1 C22.2 | length 82.1
  Top Layer w50: C21.1 C22.2@2979.72,112.5
NetD1_1: D1.1 D1.3 R1.2 T1.12 T1.13 | length 358.3
  Top Layer w100: 3462.5,1325 3667.91,1325 ; R1.2 3680.41,1394.59 3687.5,1387.5
NetD2_2: D2.2 L2.3 | length 384.5
  Bottom Layer w100: L2.3 921.85,351.57 D2.2
NetD2_3: D2.3 L2.2 | length 1239.6
  Bottom Layer w100: L2.2 273.43,226.57 375,125 1050,125 1150.39,225.39 D2.3
NetD3_1: D3.1 D5.1 | length 186.1
  Top Layer w100: D3.1@1850,1409.51 D5.1@2036.06,1409.51
NetD5_2: D5.2 R5.2 | length 155.7
  Top Layer w70: R5.2 2222.49,1251.13 D5.2
NetD6_2: D6.2 R3.2 T1.14 | length 450.5
  Top Layer w100: D6.2@3440.75,1800 3442.52,1798.23 T1.14 ; D6.2 R3.2@3447.83,1993.84 ; 3447.83,1951.97 3448.23,1952.36
NetD8_2: D8.2 R8.1 | length 103.4
  Top Layer w50: D8.2 2237.5,591.24 R8.1
NetD9_1: D9.1 D9.3 R7.2 T1.9 | length 356.3
  Top Layer w100: T1.9@3467.91,800 3651.38,800 D9.1 3667.91,862.99 R7.2
NetF1_2: F1.2 TP2.1 | length 375
  Bottom Layer w100: F1.2 TP2.1
NetQ1_1: Q1.1 R13.2 | length 335.4
  Top Layer w40: Q1.1 1803.44,848.43 1845.14,848.43 1876.54,817.03 v1(1876.54,750)
  Bottom Layer w40: v1(1876.54,750) 1876.54,748.46 1912.5,712.5 R13.2
NetQ1_3: Q1.3 R17.2 R20.2 R21.2 | length 478.8
  Top Layer w30: Q1.3 2018.9,812.5 v2(2062.5,812.5) 2060,810 2060,740 R21.2
  Bottom Layer w30: R17.2 v2(2062.5,812.5)
NetQ1_4: Q1.4 R5.1 T1.5 | length 558.3
  Top Layer w100: Q1.4@1950,1108.86 2030.83,1028.03 2180.83,1028.03 2200,1008.86 2258.86,950 T1.5
NetR2_1: R2.1 R4.2 | length 78.7
  Bottom Layer w50: R4.2 R2.1
NetR4_1: R4.1 R6.2 | length 92.9
  Bottom Layer w50: R6.2 R4.1
NetR8_2: R8.2 R12.2 T1.6 | length 835.5
  Top Layer w50: R8.2 2280.57,800 T1.6
  Bottom Layer w30: R12.2@2307.68,332.19 R12.2 2336.02,331 2387.5,382.48 2387.5,475 2525,612.5 2525,717.52 T1.6
NetR9_1: R9.1 R10.2 | length 85.8
  Bottom Layer w50: R9.1 1787.5,562.5 R10.2
NetR11_1: R11.1 R14.2 R15.2 R16.2 TP9.1 | length 585.9
  Bottom Layer w40: R16.2 3375.49,393.5 3589.57,393.5 R15.2 3691.93,383.07 R11.1 3905.32,362.5 3917.82,350 TP9.1
NetR13_1: R13.1 U1.3 | length 93.7
  Bottom Layer w25: U1.3 1933.37,450
  Bottom Layer w40: R13.1 1912.5,470.87 1933.37,450
NetR14_1: R14.1 U2.1 | length 711.3
  Bottom Layer w40: U2.1 3188.74,363.74 3281.5,456.5 3737.5,456.5 R14.1@3762.5,431.5
NetR17_1: R17.1 U1.4 | length 77.2
  Bottom Layer w25: U1.4 2062.5,445.77 R17.1
NetRT1_1: RT1.1 TP5.1 | length 404.7
  Bottom Layer w100: RT1.1 TP5.1
NetT1_3: T1.3 T1.4 | length 150
  Top Layer w100: T1.4 T1.3
PGND: C2.2 C5.2 C13.2 C14.2 C15.2 C20.2 C21.2 D2.4 R18.1 R20.1 R21.1 R24.1 R26.1 T1.7 U1.5 | length 5390.2
  Top Layer w50: C5.2 1425,637.5 1425,591.24 1425,312.5 1675,55.63 ; 1687.5,55.63 2587.5,55.63 ; v1(1775,277.36) 2392.38,277.36 2402.52,287.5 ; T1.7 2509.45,583.07 ; 2539.86,55.63 C21.2
  Top Layer w100: C5.2@1425,637.5 2062.5,637.5
  Top Layer w150: 1050,1062.5 1050,750 1175,625 1391.24,625 1425,591.24
  Bottom Layer w25: C14.2@1837.5,306 1837.5,175 1850,162.5 1974.98,162.5 1994,181.52 C20.2 R26.1 1987.48,281.52 1987.48,379.31 1995.67,387.5 U1.5 2168.5,387.5 C15.2
  Bottom Layer w30: C20.2 R24.1 ; C15.2 2331.5,394 2337.5,400 2337.5,544.98 T1.7
  Bottom Layer w50: v1(1775,277.36) 1808.86,277.36 1819,287.5 C14.2@1837.5,306
  Bottom Layer w100: D2.4 1169.49,651.57 C5.2
pads on no net: T1.1

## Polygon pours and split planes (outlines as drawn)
GND on Top Layer "Top Layer-GND" (solid, remove dead copper, pour order 42): 3400,626.17 3972.54,37.5 4850,37.5 ccw(c4842.47,107.53) 4912.5,115.06 4912.5,2102.69 ccw(c4890.68,2102.69) 4890.68,2124.51 3400,2124.51
NetC6_2 on Top Layer "Top Layer-NetC6_2" (solid, pour order 32): 3700,2125 ccw(c3700,2075) 3650,2075 3650,1762.5 ccw(c3700,1762.5) 3700,1712.5 3737.5,1712.5 ccw(c3737.5,1775) 3800,1775 3800,1782.09 cw(c3850,1782.09) 3850,1832.09 4869.59,1832.09 ccw(c4869.59,1887.5) 4925,1887.5 4925,2087.5 ccw(c4887.5,2087.5) 4887.5,2125
NetC1_2 on Top Layer "Top Layer-NetC1_2" (solid, pour order 30): 3815,1463.04 cw(c3847.68,1463.04) 3847.68,1495.72 4883.83,1495.72 cw(c4883.83,1458.22) 4921.33,1458.22 4921.33,1243.65 cw(c4885.9,1243.65) 4885.9,1208.22 3837.54,1208.22 cw(c3837.54,1230.76) 3815,1230.76
NetD9_1 on Top Layer "Top Layer-NetD9_1" (solid, pour order 28): 3400,833.61 cw(c3420.03,833.61) 3420.03,853.64 3578.64,853.64 ccw(c3578.64,875) 3600,875 cw(c3625,875) 3625,900 3725,900 cw(c3725,875) 3750,875 3750,639.96 cw(c3731.89,639.96) 3731.89,621.85 3629.73,621.85 cw(c3629.73,651.57) 3600,651.57 3600,714.35 ccw(c3562.5,714.35) 3562.5,751.85 3423.15,751.85 cw(c3423.15,775) 3400,775
NetD1_1 on Top Layer "Top Layer-NetD1_1" (solid, pour order 26): 3400,1437.5 cw(c3425,1437.5) 3425,1462.5 3714.37,1462.5 cw(c3714.37,1441.83) 3735.04,1441.83 3735.04,1235.04 cw(c3712.5,1235.04) 3712.5,1212.5 3435.24,1212.5 cw(c3435.24,1247.74) 3400,1247.74
24Vout on Top Layer "Top Layer-24Vout" (solid, pour order 20): 4831.34,621.32 ccw(c4831.34,708.82) 4918.84,708.82 4918.84,921.46 ccw(c4868.84,921.32) 4868.84,971.32 3905.48,971.32 ccw(c3896.76,893.27) 3828.86,932.74 3828.86,676.58 ccw(c3885.22,677.36) 3891.36,621.32
NetC5_1 on Top Layer "Top Layer-NetC5_1" (solid, pour order 12): 1537.5,1725 cw(c1562.5,1725) 1562.5,1750 2071.26,1750 cw(c2071.26,1721.26) 2100,1721.26 2100,1604.09 cw(c2066.18,1604.09) 2066.18,1570.28 1573.43,1570.28 cw(c1573.43,1606.2) 1537.5,1606.2
NetQ1_4 on Top Layer "Top Layer-NetQ1_4" (solid, pour order 10): 1737.07,1237.07 cw(c1762.5,1237.07) 1762.5,1262.5 2000,1262.5 cw(c2000,1250) 2012.5,1250 2012.5,1087.5 ccw(c2050,1087.5) 2050,1050 2158.86,1050 cw(c2158.86,1028.03) 2180.83,1028.03 2180.83,968.33 cw(c2175,968.33) 2175,962.5 1762.07,962.5 cw(c1762.07,987.5) 1737.07,987.5
NetQ1_3 on Top Layer "Top Layer-NetQ1_3" (solid, pour order 8): 1937.5,900 cw(c1950,900) 1950,912.5 2112.5,912.5 cw(c2112.5,887.5) 2137.5,887.5 2137.5,721.46 cw(c2128.54,721.46) 2128.54,712.5 1950,712.5 cw(c1950,725) 1937.5,725
no net on Top Layer "Top Layer-No Net" (solid, pour order 6): 1947.44,900
PGND on Top Layer "Top Layer-PGND" (solid, pour order 0): 1306.79,675 2562.5,675 cw(c2568.75,606.25) 2637.5,612.5 2637.5,87.5 cw(c2570.45,95.44) 2562.5,28.4 1365.9,28.4 cw(c1365.89,87.5) 1306.79,87.5
GND on Bottom Layer "Bottom Layer-GND" (solid, pour order 34): 3350,2062.5 cw(c3412.5,2062.5) 3412.5,2125 4862.5,2125 cw(c4862.5,2075) 4912.5,2075 4912.5,62.5 cw(c4875,62.5) 4875,25 3401.97,25 cw(c3401.97,76.97) 3350,76.97
PGND on Bottom Layer "Bottom Layer-PGND" (solid, pour order 4): 1325,651.57 cw(c1361.71,663.29) 1350,700 2508.17,700 cw(c2508.17,670.67) 2537.5,670.67 2537.5,55.63 cw(c2499.7,50.22) 2505.06,12.42 1362.5,12.42 cw(c1375.52,62.74) 1325,75
no net on Bottom Layer "Bottom Layer-No Net" (solid, pour order 2): 1625,768.75

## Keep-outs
Keep-Out Layer:
  text ".Layer_Name" at 577,-858.49 h60

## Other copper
Top Layer:
  text ".Layer_Name" at 577,-858.49 h60
Bottom Layer:
  text ".Layer_Name" at 577,-858.49 h60

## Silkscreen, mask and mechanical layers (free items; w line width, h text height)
Top Overlay:
  text "PMP30831_RevA" at 1550,1962.5 h80
  text ".Layer_Name" at 577,-858.49 h30
Bottom Overlay:
  text ".Layer_Name" at 577,-858.49 h30
Top Paste:
  text ".Layer_Name" at 577,-858.49 h60
Bottom Paste:
  text ".Layer_Name" at 577,-858.49 h60
Top Solder:
  text ".Layer_Name" at 577,-858.49 h60
  text ".Layer_Name" at 577,-858.49 h60
Bottom Solder:
  text ".Layer_Name" at 577,-858.49 h60
Drill Guide:
  text ".Layer_Name" at 577,-858.49 h60
M1 Board Outline:
  the board outline again, w10
  text ".Layer_Name" at 577,-858.49 h60
M2 Board Dimensions:
  rectangle: 0,-275 125,-150
  rectangle: 125,-400 500,-275
  lines w7: 0,-275 1000,-275 ; 125,-400 125,-150 ; 250,-400 250,-150 ; 500,-400 500,-150 ; 750,-400 750,-150 ; 0,-400 1000,-400 1000,-150 0,-150 0,-400
  text ".Layer_Name" at 577,-858.49 h60
M3 3D STEP Top:
  text ".Layer_Name" at 577,-858.49 h60
M4 3D STEP Bottom:
  text ".Layer_Name" at 577,-858.49 h60
M5 Assembly Top:
  lines w10: -292,-930.17 6308,-930.17 ; -292,-726.83 6310,-726.83 ; -292,-523.5 -292,-1133.5 3713,-1133.5 6310,-1133.5 6310,-523.5 -291.5,-523.5 -291.5,-1133.5 1284,-1133.5 ; 2173,-1133.5 2173,-523.5 ; 3440,-726.83 3440,-523.5 ; 4280,-726.83 4280,-523.5 ; 4902,-1140 4902,-937.17
  text "COMPONENTS MARKED 'DNP' SHOULD NOT BE POPULATED." at 1153.5,-318.5 h60
  text "ASSEMBLY VARIANT:" at 1153,-434 h60
  text ".VariantName" at 2189,-434 h60
  text "PCB VIEWED FROM TOP SIDE" at -228.5,-655.67 h60
  text "BOARD #:" at 2248,-655.67 h60
  text ".PRJ_Number" at 2793.5,-655.67 h60
  text "REV:" at 3638,-655.67 h60
  text ".PCB_Rev" at 3929.5,-655.67 h60
  text "SVN REV:" at 4476,-655.67 h60
  text ".VersionControl_RevNumber" at 4982,-655.67 h60
  text "TID #:" at 2248,-859 h60
  text ".TID" at 2793.5,-859 h60
  text "PLOT NAME =" at -228.5,-1064.34 h60
  text ".plot_File_Name" at 577,-1064.34 h60
  text "GENERATED    :" at 2250,-1064.34 h60
  text ".Print_Date" at 3119.5,-1064.34 h60
  text ".Print_Time" at 3848.5,-1064.34 h60
  text "TEXAS INSTRUMENTS" at 5113,-1064.34 h60
M6 Assembly Bottom:
  lines w10: -292.5,-727.33 6309.5,-727.33 ; -290.5,-930.67 6309.5,-930.67 ; 1115.5,-1140.5 1115.5,-937.67 ; 1737.5,-727.33 1737.5,-524 ; 2577.5,-727.33 2577.5,-524 ; 3844.5,-1134 3844.5,-524 ; 4733.5,-1134 6309,-1134 6309,-524 -292.5,-524 -292.5,-1134 2304.5,-1134 6309.5,-1134 6309.5,-524
  text "COMPONENTS MARKED 'DNP' SHOULD NOT BE POPULATED." at 6102,-318 h60
  text ".VariantName" at 5058,-434 h60
  text "ASSEMBLY VARIANT:" at 6097,-434 h60
  text ".VersionControl_RevNumber" at 1035.5,-656.17 h60
  text "SVN REV:" at 1541.5,-656.17 h60
  text ".PCB_Rev" at 2088,-656.17 h60
  text "REV:" at 2379.5,-656.17 h60
  text ".PRJ_Number" at 3224,-656.17 h60
  text "BOARD #:" at 3769.5,-656.17 h60
  text "PCB VIEWED FROM BOTTOM SIDE" at 6246,-656.17 h60
  text ".TID" at 3224,-859.5 h60
  text "TID #:" at 3769.5,-859.5 h60
  text "TEXAS INSTRUMENTS" at 904.5,-1064.84 h60
  text ".Print_Time" at 2169,-1064.84 h60
  text ".Print_Date" at 2898,-1064.84 h60
  text "GENERATED    :" at 3767.5,-1064.84 h60
  text ".plot_File_Name" at 5440.5,-1064.84 h60
  text "PLOT NAME =" at 6246,-1064.84 h60
M9 Title Sheet:
  drawing of 55 lines, arcs and shapes, not listed
  text "1" at 739.84,8036.5 h70
  text "2" at 3235.5,8036.5 h70
  text "3" at 5724.84,8036.5 h70
  text "4" at 8231.51,8036.5 h70
  text "5" at 10730.5,8036.5 h70
  text "6" at 13235.5,8036.5 h70
  text "A" at -416.5,6893.5 h70
  text "A" at 14383.5,6893.5 h70
  text "B" at -416.5,4513.5 h70
  text "B" at 14383.5,4513.5 h70
  text "C" at -416.5,2138.5 h70
  text "C" at 14383.5,2138.5 h70
  text "PROJECT TITLE:" at 11343.5,277.5 h45
  text ".PRJ_Title" at 11393.5,144.17 h70
  text "DESIGNED FOR:" at 11343.5,-23.5 h45
  text ".PRJ_Customer" at 11393.5,-163.5 h70
  text "D" at -416.5,-231.5 h70
  text "D" at 14383.5,-231.5 h70
  text "FILE NAME:" at 11343.5,-323.5 h45
  text ".PCB_File_Name_No_Path" at 11393.5,-443.5 h70
  text "Texas Instruments (TI) and/or its licensors do not warrant the accuracy or completeness of this specification" at 6374,-605.34 h45
  text "ENGINEER:" at 11343.5,-613.5 h45
  text "LAYOUT BY:" at 12848.5,-613.5 h45
  text "or any information contained therein. TI and/or its licensors do not warrant that this design will meet" at 6329.01,-718 h45
  text ".PRJ_Engineer" at 11393.5,-768.49 h70
  text ".PCB_Layout" at 12899,-768.49 h70
  text "the specifications, will be suitable for your application or fit for any particular purpose, or will operate in" at 6329.01,-830.67 h45
  text ".Layer_Name" at 577,-858.49 h60
  text "ALTIUM DESIGNER VERSION:" at 12848.5,-923.5 h45
  text "an implementation. TI and/or its licensors do not warrant that the design is production worthy. You should" at 6329.01,-943.33 h45
  text "completely validate and test your design implementation to confirm the system functionality for your application." at 6374,-1056 h45
  text ".print_Scale" at 11393.5,-1056.83 h70
  text ".Application_BuildNumber" at 12899,-1056.83 h70
  text "1" at 739.84,-1263.5 h70
  text "2" at 3235.5,-1263.5 h70
  text "3" at 5724.84,-1263.5 h70
  text "4" at 8231.51,-1263.5 h70
  text "5" at 10730.5,-1263.5 h70
  text "6" at 13235.5,-1263.5 h70
M10 Fab Notes:
  text ".Layer_Name" at 577,-858.49 h60
M11 Gerber Information:
  lines w10: -292,-930.17 6308,-930.17 ; -292,-726.83 6310,-726.83 ; -292,-523.5 -292,-1133.5 3713,-1133.5 6310,-1133.5 6310,-523.5 -291.5,-523.5 -291.5,-1133.5 1284,-1133.5 ; 2173,-1133.5 2173,-523.5 ; 3440,-726.83 3440,-523.5 ; 4280,-726.83 4280,-523.5 ; 4902,-1140 4902,-937.17
  text "ALL ARTWORK VIEWED FROM TOP SIDE" at -228.5,-655.67 h60
  text "BOARD #:" at 2248,-655.67 h60
  text ".PRJ_Number" at 2793.5,-655.67 h60
  text "REV:" at 3638,-655.67 h60
  text ".PCB_Rev" at 3929.5,-655.67 h60
  text "SVN REV:" at 4476,-655.67 h60
  text ".VersionControl_RevNumber" at 4982,-655.67 h60
  text "LAYER NAME =" at -228.5,-858.49 h60
  text "TID #:" at 2248,-859 h60
  text ".TID" at 2793.5,-859 h60
  text "PLOT NAME =" at -228.5,-1064.34 h60
  text ".plot_File_Name" at 577,-1064.34 h60
  text "GENERATED    :" at 2250,-1064.34 h60
  text ".Print_Date" at 3119.5,-1064.34 h60
  text ".Print_Time" at 3848.5,-1064.34 h60
  text "TEXAS INSTRUMENTS" at 5113,-1064.34 h60
M12 Stackup:
  text ".Layer_Name" at 577,-858.49 h60
M13 Component Bodies Top:
  text ".Layer_Name" at 577,-858.49 h60
M14 Component Bodies Bottom:
  text ".Layer_Name" at 577,-858.49 h60
M15 Courtyards Top:
  text ".Layer_Name" at 577,-858.49 h60
M16 Courtyards Bottom:
  text ".Layer_Name" at 577,-858.49 h60
Drill Drawing:
  text ".Layer_Name" at 577,-858.49 h60
M17 Embedded Cavity:
  text ".Layer_Name" at 577,-858.49 h60
M18 Embedded Assembly:
  text ".Layer_Name" at 577,-858.49 h60
M19 Embedded Keepout:
  text ".Layer_Name" at 577,-858.49 h60

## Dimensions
0,-400 to 1000,-400 on M2 Board Dimensions
0,0 to 0,2150 on M2 Board Dimensions
0,0 to 4950,0 on M2 Board Dimensions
